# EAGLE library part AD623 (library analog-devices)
Single-Supply, Rail-to-Rail, Low Cost Instrumentation Amplifier Source: http://www.analog.com/static/imported-files/data_sheets/AD623.pdf
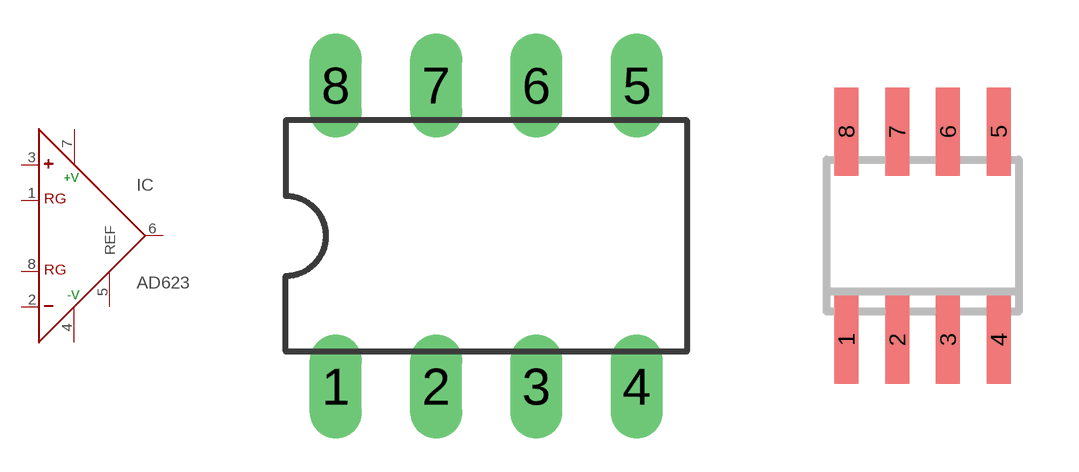
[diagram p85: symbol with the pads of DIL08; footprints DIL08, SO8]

Designator prefix IC

## AD623N (MF: ALTERA CORPORATION; MPN: AD623ANZ; OC_FARNELL: 9603700; OC_NEWARK: 59K4402)  [DIL08]
1  RG  pas
2  -  in
3  +  in
4  -V  pwr
5  REF  pas
6  OUT  out
7  +V  pwr
8  RG  pas

## AD623R (MPN: AD623ARZ.; OC_FARNELL: 9426213; OC_NEWARK: 31M4186)  [SO8]
Pads as for DIL08

## AD623RM (MPN: AD623ARMZ; OC_FARNELL: 1660961; OC_NEWARK: 19M8824)  [MSOP08]
Pads as for DIL08

## Footprint DIL08 (pad centres in mm)
Dual In Line Package
drill 0.813 long: 1 -3.81,-3.81; 2 -1.27,-3.81; 3 1.27,-3.81; 4 3.81,-3.81; 5 3.81,3.81; 6 1.27,3.81; 7 -1.27,3.81; 8 -3.81,3.81

## Footprint SO8 (pad centres in mm)
8-Lead Small Outline IC (SO-8) Source: http://www.analog.com/UploadedFiles/Data_Sheets/703465986AD8611_2_0.pdf
smd 0.6 x 2.2: 1 -1.905,-2.6; 2 -0.635,-2.6; 3 0.635,-2.6; 4 1.905,-2.6; 5 1.905,2.6; 6 0.635,2.6; 7 -0.635,2.6; 8 -1.905,2.6

## Footprint MSOP08 (pad centres in mm)
8-Lead micro SO (RM-8) Source: http://www.analog.com/UploadedFiles/Data_Sheets/703465986AD8611_2_0.pdf
smd 0.4 x 1: 1 -0.976,-2.263; 2 -0.326,-2.263; 3 0.324,-2.263; 4 0.974,-2.263; 5 0.974,2.262; 6 0.324,2.262; 7 -0.326,2.262; 8 -0.976,2.262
